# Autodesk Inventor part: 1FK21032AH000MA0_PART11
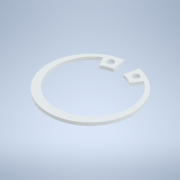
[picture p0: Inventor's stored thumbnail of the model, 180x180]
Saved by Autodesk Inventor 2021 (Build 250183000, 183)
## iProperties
Created: 2025-04
Part Number: 1FK21032AH000MA0_PART11
Material: Generic
Catalog Web Link: www.3dfindit.com
Description: -Servo synchronous motor
Document SubType Name: Modeling
Designer: psAdmin
Mass: 0.288797 g
Surface Area: 7.43416 cm^2
Volume: 0.288797 cm^3
Density: 1 g/cm^3
Appearance: PSOLRGB-212-217-219
Category: PARTsolutions
Title: 1FK21032AH000MA0_PART11
Author: Cadenas PARTsolutions
Comments: Servo synchronous motor
Sending System: PARTsolutions
Preprocessor: ST-DEVELOPER v19.3
PSOL_IDENT_0: {$CADENAS_DATA/23d-libs/siemens_ag/_cat_/45/10/1fk21032ah000ma0.prj},216 {VTYP=3D},{NB=1FK21032AH000
PSOL_IDENT_1: MA0_PART11},{LINA=1FK21032AH000MA0_PART11},{NN=1FK21032AH000MA0_PART11},{NOPRJ=TRUE},{DATE=19.08.202
PSOL_IDENT_2: 5 14:00:35},{GEOMDATE=30.07.2025 02:02:03},{VERSION=},{LINEID=10},{WBVAR=},{WBNUMERIC=}  {NB=1FK2103
PSOL_IDENT_3: 2AH000MA0_PART11},{LINA=1FK21032AH000MA0_PART11},{KT=DUMMY},{PREVIEW=../../../_pool_/14/8e/p_d211_xx
PSOL_IDENT_4: _00426j.png},{DESCSHORT=SIMOTICS S-1FK2 HD, SINAMICS S210 3AC 400V-480V, 0.59 Nm, 4500 rpm},{DESCLON
PSOL_IDENT_5: G=SIMOTICS S-1FK2 HD servo motor M0=0.64 Nm; PN = 0.28 kW at nN=4500 rpm (380-480 V); PN = 0.167 kW
PSOL_IDENT_6: at nN=2500 rpm (200-240 V); degree of protection IP64; cylindrical shaft D14 x 30 mm; absolute encod
PSOL_IDENT_7: er 22-bit + 12-bit multiturn (encoder AM22DQC); with OCC interface; plug size M17, rotatable; SIMOTI
PSOL_IDENT_8: CS S-1FK2 servomotorfor a wide range of uses in industrial environments. SIMOTICS S‑1FK2 servomotors
PSOL_IDENT_9: are compact synchronous motors with a high dynamic performance that set themselves apart as a resul
PSOL_IDENT_10: t of their high power density, degree of protection and overload capability. The motors are availabl
PSOL_IDENT_11: e in two variants: as High Dynamic variant (highest dynamic performance as a result of the low intri
PSOL_IDENT_12: nsic moment of inertia for applications demanding a high dynamic performance with low moved masses)
PSOL_IDENT_13: - and as Compact variant (precise and stable closed-loop control for medium up to large moved masses
PSOL_IDENT_14: as a result of a medium intrinsic moment of inertia). SIMOTICSS‑1FK2 servomotors fully exploit thei
PSOL_IDENT_15: r strengths in a system with the SINAMICSS210 frequency converter and simple connection using the on
PSOL_IDENT_16: e cable connection (OCC). Advantages include the short control and positioning times, fast and preci
PSOL_IDENT_17: se correction of disturbing quantities as well as stable control with a high dynamic performance. Th
PSOL_IDENT_18: e servo motors can be configured to address a wide range of requirements. For example with and witho
PSOL_IDENT_19: ut holding brake, IP64 or IP65 degree of protection, singleturn or multiturn absolute encoders - to
PSOL_IDENT_20: name just a few. Further, the servomotors are available in different shaft heights extending from 20
PSOL_IDENT_21: to 100. A shaft sealing ring is available to achieve an IP65 degree of protection and for subsequen
PSOL_IDENT_22: t mounting at the motor or as spare part. SIMOTICS - the optimum motor for each and every motion con
PSOL_IDENT_23: trol application.},{INTNO=195125335004},{SUPPLIERALTNO=1FK2103-2AH00-0MA0},{MANUID=1FK21032AH000MA0}
PSOL_IDENT_24: ,{MANUNAME=Siemens},{MANUTYPEDESC=SYNCHRONOUS MOTOR 1FK2 HD 0,64 NM},{AAU732=SIMOTICS},{AAO057=S-1FK
PSOL_IDENT_25: 2},{AAU734=SIMOTICS S-1FK2 HD servo motor M0=0.64 Nm; PN = 0.28 kW at nN=4500 rpm (380-480 V); PN =
PSOL_IDENT_26: 0.167 kW at nN=2500 rpm (200-240 V); degree of protection IP64; cylindrical shaft D14 x 30 mm; absol
PSOL_IDENT_27: ute encoder 22-bit + 12-bit multiturn (encoder AM22DQC); with OCC interface; plug size M17, rotatabl
PSOL_IDENT_28: e;},{AAW338=SYNCHRONOUS MOTOR 1FK2 HD 0,64 NM},{AAO742=SIMOTICS},{AAO663=4034106444624},{NOCUPEROU=1
PSOL_IDENT_29: },{PRICEQUANTITY=1},{QUANTITYMIN=1},{QUANTITYINT=1},{CTN=85015100},{COO=RO},{AAO676=1FK2103-2AH00-0M
PSOL_IDENT_30: A0},{AAO677=Siemens AG},{ORDERUNIT=C62},{CONTENTUNIT=C62}
NB: 1FK21032AH000MA0_PART11
NT: Servo synchronous motor
NBSYN: $MANUID._PART11
LINA: 1FK21032AH000MA0_PART11
CATALOG: SIEMENS
PREVIEW: ../../../_pool_/14/8e/p_d211_xx_00426j.png
DESCSHORT: SIMOTICS S-1FK2 HD, SINAMICS S210 3AC 400V-480V, 0.59 Nm, 4500 rpm
DESCLONG: SIMOTICS S-1FK2 HD servo motor M0=0.64 Nm; PN = 0.28 kW at nN=4500 rpm (380-480 V); PN = 0.167 kW at nN=2500 rpm (200-240 V); degree of protection IP64; cylindr
INTNO: 195125335004
SUPPLIERALTNO: 1FK2103-2AH00-0MA0
MANUID: 1FK21032AH000MA0
MANUNAME: Siemens
MANUTYPEDESC: SYNCHRONOUS MOTOR 1FK2 HD 0,64 NM
AAU732: SIMOTICS
AAO057: S-1FK2
AAU734: SIMOTICS S-1FK2 HD servo motor M0=0.64 Nm; PN = 0.28 kW at nN=4500 rpm (380-480 V); PN = 0.167 kW at nN=2500 rpm (200-240 V); degree of protection IP64; cylindr
AAW338: SYNCHRONOUS MOTOR 1FK2 HD 0,64 NM
AAO742: SIMOTICS
AAO663: 4034106444624.0
NOCUPEROU: 1
PRICEQUANTITY: 1
QUANTITYMIN: 1
QUANTITYINT: 1
CTN: 85015100
COO: RO
ARTICLENO: 1FK21032AH000MA0_PART11
BOMINFO: 1FK21032AH000MA0_PART11
CREATOR: CADENAS GmbH
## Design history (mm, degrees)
feature "2025_04_17_15_00_20_0760"
body "Solid1"
